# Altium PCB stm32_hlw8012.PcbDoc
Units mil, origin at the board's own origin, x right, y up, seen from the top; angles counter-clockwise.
Board outline 2529.53 x 3198.82 mil, 2 copper layers (Top Layer, Bottom Layer); 72 components, 57 nets, 229 pads, 39 vias.
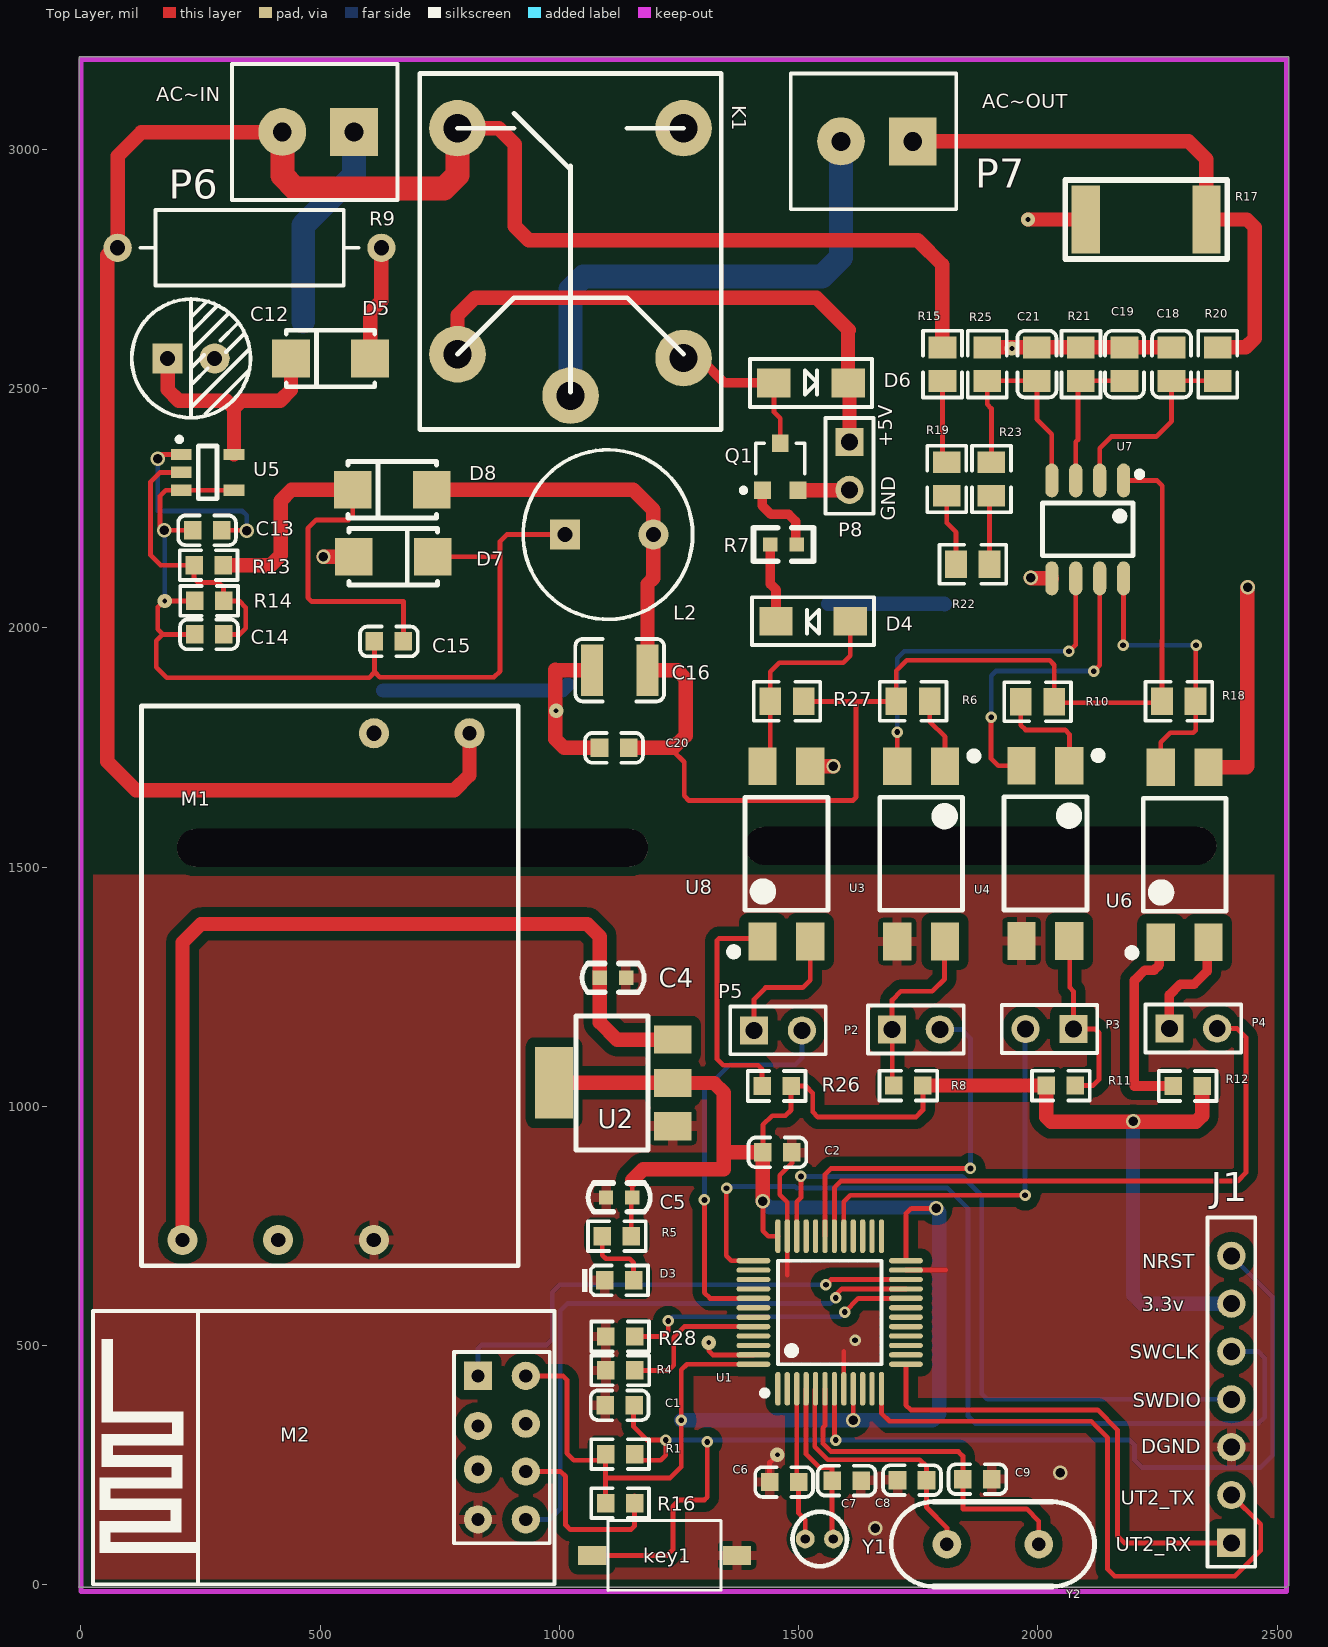
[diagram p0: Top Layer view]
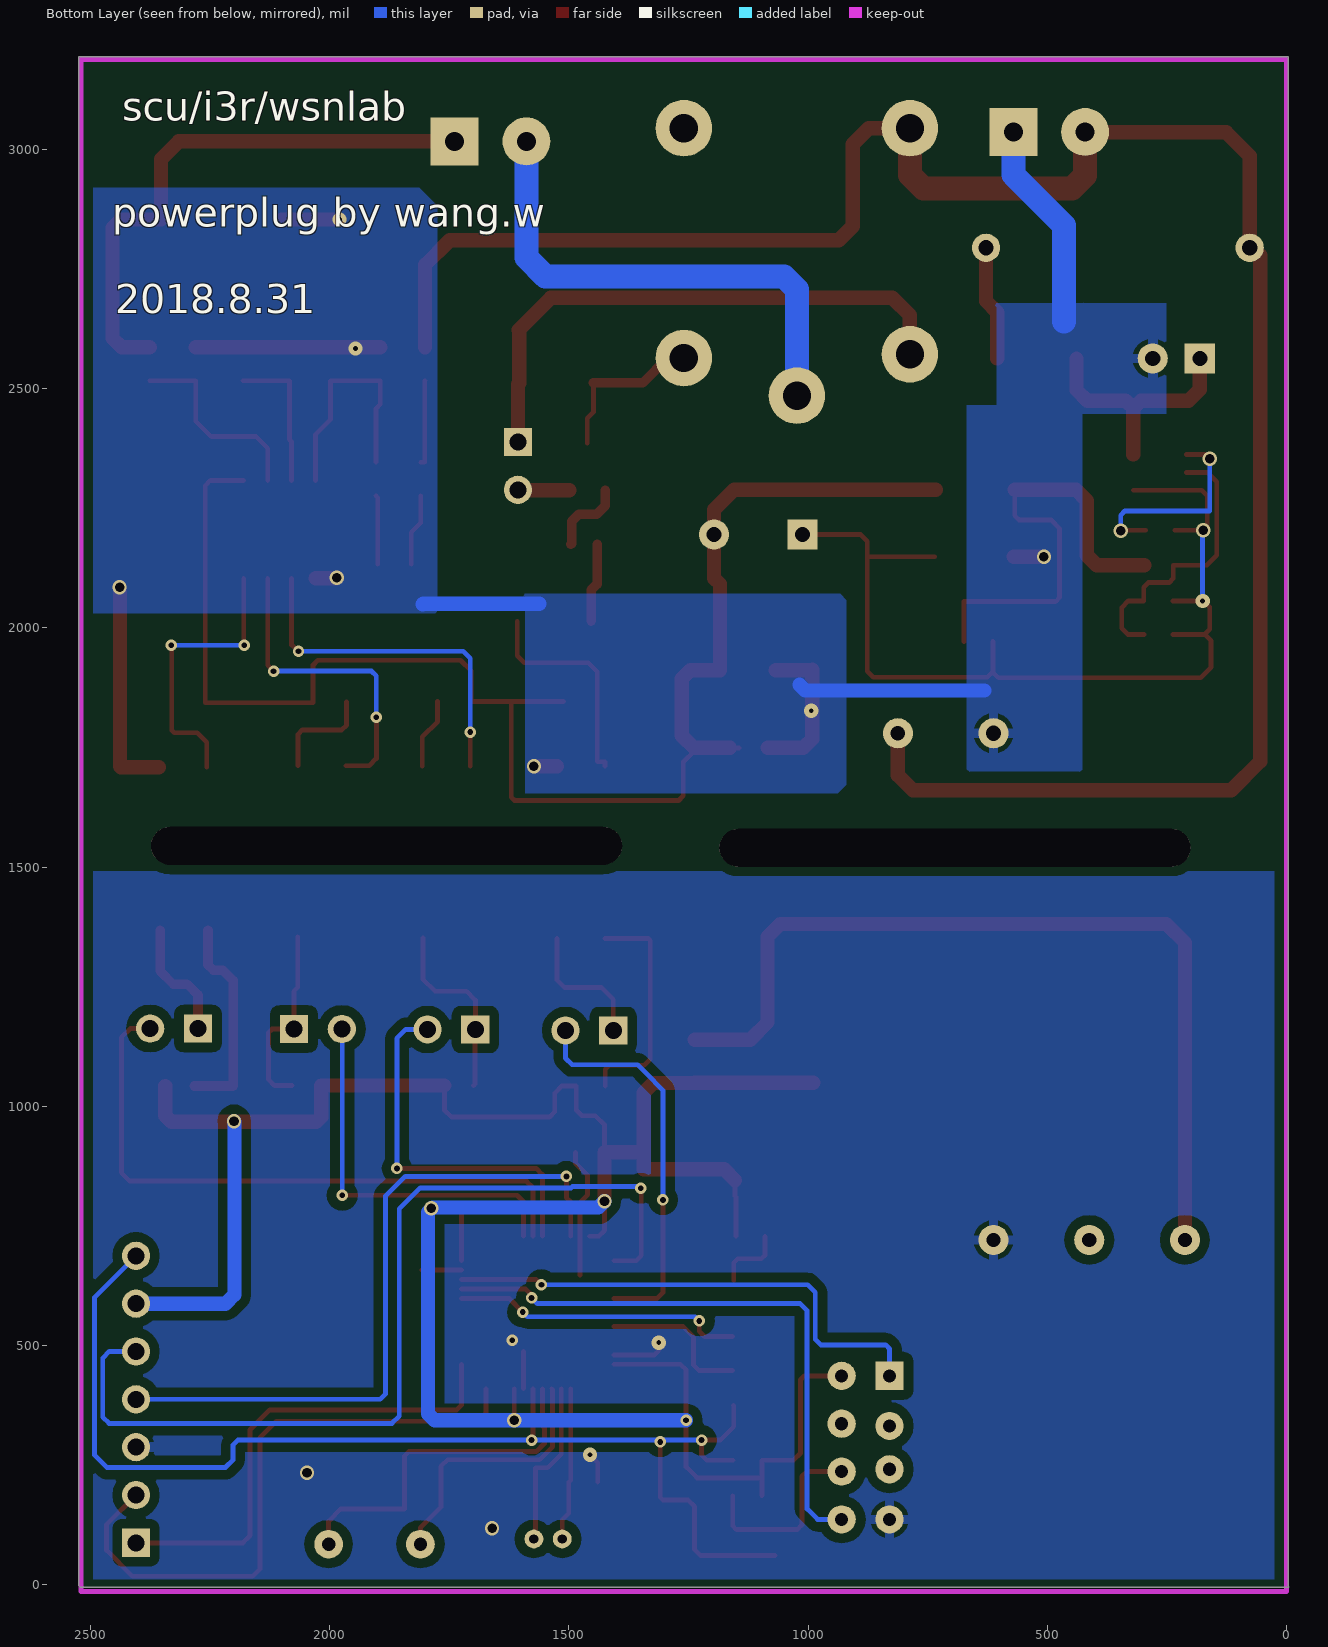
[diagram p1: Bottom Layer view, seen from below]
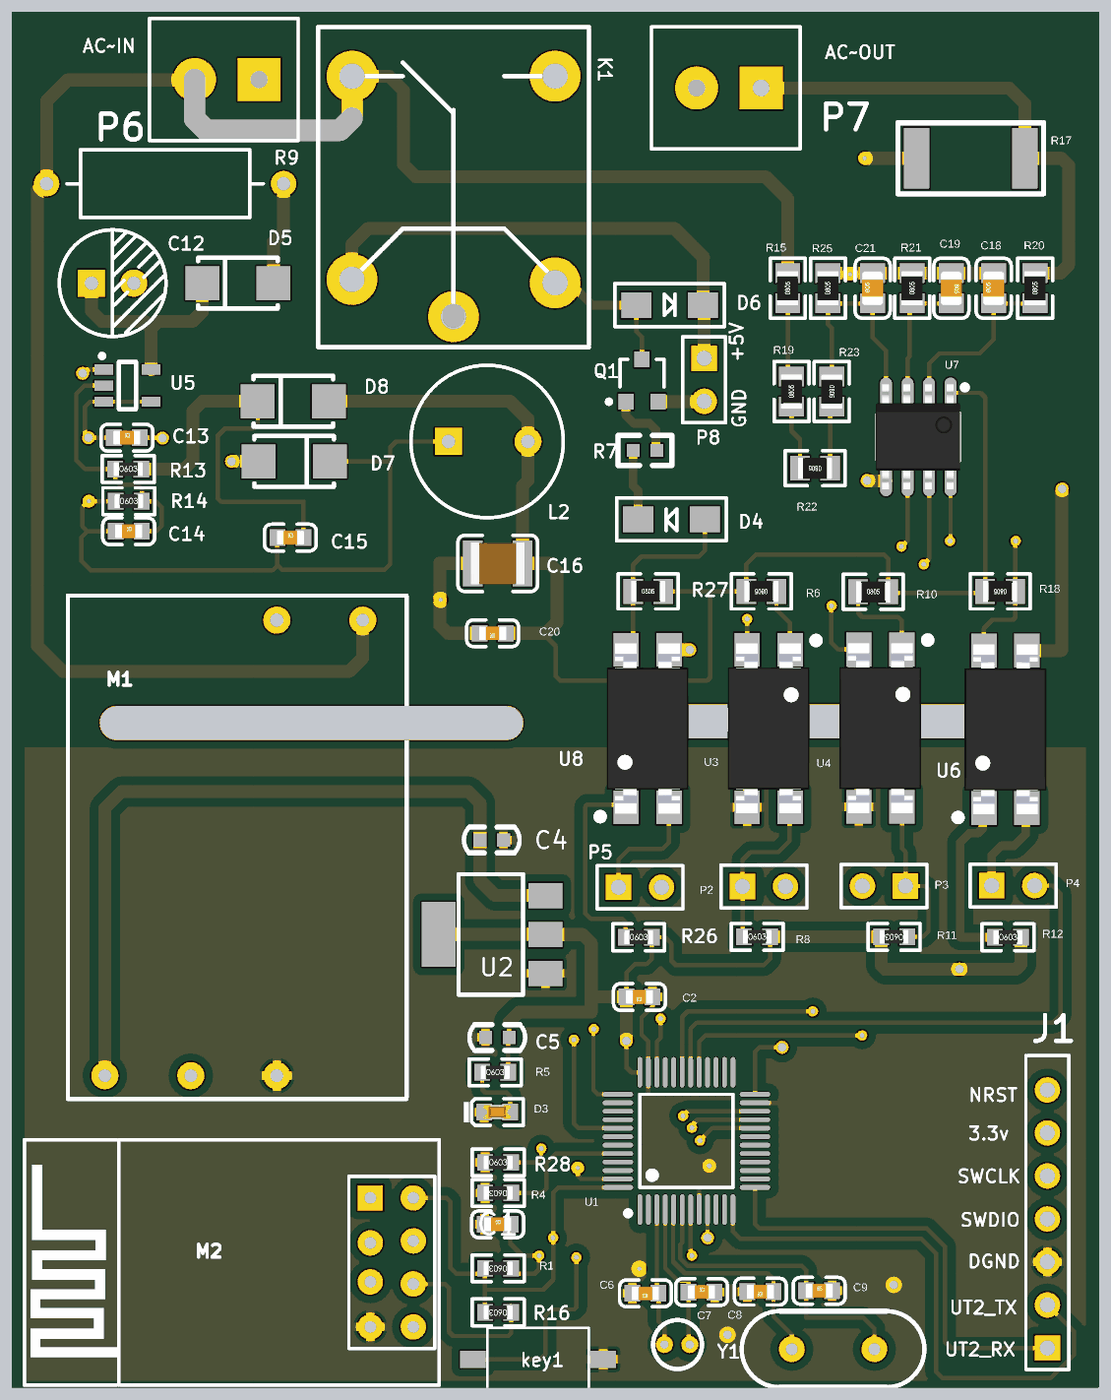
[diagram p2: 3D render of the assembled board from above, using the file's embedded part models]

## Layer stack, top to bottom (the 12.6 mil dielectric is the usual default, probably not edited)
Top Solder: solder mask 0.4, Solder Resist, Dk 3.5
Top Layer: signal copper 1.4
Dielectric 1: dielectric 12.6, FR-4, Dk 4.8
Bottom Layer: signal copper 1.4
Bottom Solder: solder mask 0.4, Solder Resist, Dk 3.5

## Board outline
2524.61,3193.9 2524.61,-1.97 2521.65,-4.92 -4.92,-4.92 -3.94,-3.94 -3.94,3193.9

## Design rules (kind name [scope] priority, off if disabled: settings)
Clearance Clearance_1 [InPolygon] p1: gap=20 ignorepadtopadclearanceinfootprint=FALSE except(0: Arc-Hole Track-Hole SMDPad-Hole THPad-Hole Via-Hole Fill-Hole Poly-Hole Region-Hole Text-Hole)
Clearance [All] p2: gap=7 ignorepadtopadclearanceinfootprint=FALSE except(0: Arc-Hole Track-Hole SMDPad-Hole THPad-Hole Via-Hole Fill-Hole Poly-Hole Region-Hole Text-Hole)
ComponentClearance [All] p1: gap=4 collisioncheckmode=3 verticalgap=4 showdistances=FALSE
DiffPairsRouting [All] p1: maxlimit=10 minlimit=10 mostfreqgap=10 toplayer_minwidth=10 toplayer_maxwidth=15 toplayer_prefwidth=15 bottomlayer_minwidth=10 bottomlayer_maxwidth=15 bottomlayer_prefwidth=15 maxuncoupledlength=500
HoleSize [All] p1: absolutevalues=TRUE maxlimit=500 minlimit=1 maxpercent=80.000 minpercent=20.000
HoleToHoleClearance [All] p1: gap=4 allowstackedmicrovias=TRUE
MinimumSolderMaskSliver [All] p1: minsoldermaskwidth=4
PolygonConnect PolygonConnect_1 [Isvia] p1: connectstyle=Direct reliefconductorwidth=10 reliefentries=4 polygonreliefangle="90 Angle" airgapwidth=10
PolygonConnect [All] p2: connectstyle=Relief reliefconductorwidth=20 reliefentries=4 polygonreliefangle="90 Angle" airgapwidth=10
RoutingVias [All] p1: holewidth=20 width=30 viastyle="Through Hole" minholewidth=10 minwidth=10 maxholewidth=28 maxwidth=50
SilkToSilkClearance [All] p1: silktosilkclearance=4
SilkToSolderMaskClearance [IsPad] p1: minsilkscreentomaskgap=0 clearancetoexposedcopper=TRUE
SolderMaskExpansion [All] p1: expansion=4
Width [All] p1: maxlimit=500 minlimit=10 preferedwidth=10 minimp=50.000000 maximp=50.000000 favimp=50.000000
23 further rules are at their usual default settings.

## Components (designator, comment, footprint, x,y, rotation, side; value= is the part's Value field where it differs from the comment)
C1 "0.1μF" LC-0603_C 1125.98,375 r0 top
C2 "0.1μF" LC-0603_C 1455.71,903.54 r180 top
C4 "104" 0603C 1106.3,1269.69 r180 top
C5 "104" 0603C 1130.91,808.07 r0 top
C6 "6pF" LC-0603_C 1469.69,214.57 r180 top
C7 "6pF" LC-0603_C 1600.2,217.52 r0 top
C8 "20pF" LC-0603_C 1737.01,218.5 r180 top
C9 "20pF" LC-0603_C 1873.82,220.47 r0 top
C12 "3.3μF/400V" CAP-ELECT-TH-6.3X7 230.31,2562.99 r0 top value=2.2μF/400V
C13 "2.2μF/10V" LC-0603_C 263.58,2203.74 r0 top value="100nF (104) ±10% 50V"
C14 "470pF" LC-0603_C 267.72,1986.22 r0 top value="100nF (104) ±10% 50V"
C15 "220nF" LC-0603_C 643.7,1971.46 r0 top value="100nF (104) ±10% 50V"
C16 "100μF" LC-1210_C 1125.98,1911.42 r0 top value="100nF (104) ±10% 50V"
C18 "33nF" LC-0805_C 2279.53,2551.18 r90 top value="100nF (104) ±10% 50V"
C19 "33nF" LC-0805_C 2181.1,2551.18 r270 top value="100nF (104) ±10% 50V"
C20 "0.1μF" LC-0603_C 1114.17,1749.02 r180 top value="100nF (104) ±10% 50V"
C21 "33nF" LC-0805_C 1998.03,2551.18 r90 top value="100nF (104) ±10% 50V"
D3 "POWER" LC-0603_LED_S1 1124.8,635.83 r0 top value=红色
D4 "IN4148" 1206D 1657.76,2043.78 r270 top
D5 "1N4007" LC-SMA(DO-214AC)_S1 521.65,2562.99 r0 top
D6 "" 1206D 1398.35,2481.81 r90 top
D7 "US1J(600V 1A)" LC-SMA(DO-214AC)_S1 652.56,2148.62 r180 top
D8 "1N4007" LC-SMA(DO-214AC)_S1 650.59,2288.39 r0 top
J1 "4P/NC" HDR1X7 2404.53,87.4 r90 top
K1 "Relay-5V" RLAYSPDT 983.27,2805.12 r90 top
key1 "SW" KEY-2 1371.06,61.02 r180 top
L2 "1mH" L-10X14 1101.38,2194.88 r0 top
M1 "ACDC_THX208based" ACDC_THX208 911.42,1836.61 r270 top
M2 "ESP-01&01S Module" "ESP-01&01S Module" 879.72,286.42 r90 top
P2 "Header" HDR1X2 1695.28,1160.43 r0 top
P3 "Header" HDR1X2 2074.41,1161.42 r180 top
P4 "Header" HDR1X2 2275,1162.4 r0 top
P5 "Header" HDR1X2 1406.89,1158.47 r0 top
P6 "Header" 3.81-2P 570.87,3037.4 r180 top
P7 "Header" 3.81-2P 1738.58,3017.73 r180 top
P8 "Header" HDR1X2 1606.3,2388.39 r270 top
Q1 "S8050" SOT-23 1461.61,2336.61 r0 top
R1 "10KΩ" LC-0603_R 1126.97,272.64 r180 top
R4 "10KΩ" LC-0603_R 1127.17,447.83 r180 top
R5 "1.5KΩ" LC-0603_R 1120.08,728.35 r0 top
R6 "1KΩ,1%" LC-0805_R 1739.17,1846.46 r180 top
R7 "Res2" 0603 1495.94,2174.21 r180 top value=4.7K
R8 "2.2KΩ" LC-0603_R 1729.53,1043.31 r0 top
R9 "39Ω/1W" R-1W-THT 352.36,2794.29 r0 top
R10 "1KΩ,1%" LC-0805_R 1999.41,1845.47 r0 top
R11 "2.2KΩ" LC-0603_R 2048.03,1043.31 r180 top
R12 "2.2KΩ" LC-0603_R 2312.99,1042.32 r0 top
R13 "5.49KΩ" LC-0603_R 266.73,2130.91 r0 top
R14 "4.99KΩ" LC-0603_R 267.91,2056.1 r0 top
R15 "470KΩ,1%" LC-0805_R 1800.59,2551.18 r90 top
R16 "4.7KΩ" LC-0603_R 1126.97,170.28 r180 top
R17 "2mΩ/25A" R2512 2226.38,2853.35 r180 top
R18 "1KΩ,1%" LC-0805_R 2294.88,1846.46 r180 top
R19 "470KΩ,1%" LC-0805_R 1809.45,2311.02 r90 top
R20 "1KΩ,1%" LC-0805_R 2375.98,2551.18 r90 top
R21 "1KΩ,1%" LC-0805_R 2089.98,2551.18 r90 top
R22 "470KΩ,1%" LC-0805_R 1864.17,2132.87 r180 top
R23 "470KΩ,1%" LC-0805_R 1902.95,2311.02 r270 top
R25 "1KΩ,1%" LC-0805_R 1894.09,2551.18 r90 top
R26 "2.2KΩ" LC-0603_R 1453.94,1042.32 r0 top
R27 "1KΩ,1%" LC-0805_R 1475.79,1846.46 r0 top
R28 "10KΩ" LC-0603_R 1126.97,518.7 r0 top
U1 "STM32F103C8T6" LC-LQFP-48_7x7x05P 1564.96,568.9 r0 top
U2 "LM1117-3.3V" SOT-223/P2.3 1125.98,1047.24 r180 top
U3 "PC817" LC-SMD-4 1756.1,1527.56 r270 top
U4 "PC817" LC-SMD-4 2015.95,1528.54 r270 top
U5 "MP150" LC-SOT-23-5 264.76,2324.8 r180 top
U6 "PC817" LC-SMD-4 2306.89,1525.59 r90 top
U7 "HLW8012" LC-SOP-8_150mil 2104.33,2205.71 r180 top
U8 "PC817" LC-SMD-4 1474.61,1527.56 r90 top
Y1 "32.768K" CRYSTAL 1522.83,95.47 r180 top
Y2 "8M" 49/U_N 1810.04,84.64 r0 top value="25MHz ±20ppm 20pF"

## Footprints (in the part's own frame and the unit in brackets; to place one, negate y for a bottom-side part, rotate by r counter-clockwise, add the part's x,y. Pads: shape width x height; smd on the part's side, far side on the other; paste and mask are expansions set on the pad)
3.81-2P [mil]
  rect 100x100 hole 39.37: 1(0,0.99)
  round 100 hole 39.37: 2(150,1)
  silkscreen extent -91,-141 255,143
49/U_N [mil]
  round 60 hole 28: 1(0,0) 2(192,0)
  silkscreen extent -116,-88 308,89, body extent -117,-88 309,89, height 512
0603 [mil]
  rect 30x30 smd: 1(0,0) 2(55,0)
  silkscreen extent -35,-35 90,35
0603C [mil]
  rect 30x30 smd: 1(21.61,1.26) 2(-33.39,1.26)
  silkscreen extent -71,-29 59,31
1206D [mil]
  rect 60x70 smd: 1(30,-50) 2(30,-205)
  silkscreen extent -20,-255 80,0
ACDC_THX208 [mm]
  round 1.6 hole 0.762: 1(1.45,-2.52) 3(28.35,-7.6) 4(28.35,-12.68) 5(28.35,-17.76)
  round 1.6 hole 0.8: 2(1.45,-7.6)
  silkscreen extent 0,-19.94 29.72,0.06
CAP-ELECT-TH-6.3X7 [mm]
  rect 1.6x1.6 hole 0.8: 1(-1.25,0)
  round 1.6 hole 0.8: 2(1.25,0)
  silkscreen extent -3.15,-3.15 3.15,3.15
CRYSTAL [mm]
  round 1 hole 0.5: 1(-1.27,0) 2(0.23,0)
  silkscreen extent -1.99,-1.44 0.9,1.44
"ESP-01&01S Module" [mm]
  rect 1.5x1.5 hole 0.7: 1(3.81,1.27)
  round 1.5 hole 0.7: 2(1.15,1.27) 3(-1.15,1.27) 4(-3.81,1.27) 5(3.81,-1.27) 6(1.27,-1.27) 7(-1.27,-1.27) 8(-3.81,-1.27)
  silkscreen extent -7.25,-2.79 7.25,21.71
HDR1X2 [mm] "Connector; Header; 2 Position"
  rect 1.5x1.5 hole 0.9: 1(0,0)
  round 1.5 hole 0.9: 2(2.54,0)
  silkscreen extent -1.27,-1.27 3.81,1.27
HDR1X7 [mm]
  rect 1.5x1.5 hole 0.9: 1(0,0)
  round 1.5 hole 0.9: 2(2.54,0) 3(5.08,0) 4(7.62,0) 5(10.16,0) 6(12.7,0) 7(15.24,0)
  silkscreen extent -1.27,-1.27 17.27,1.27
KEY-2 [mm]
  rect 1.5x1 smd: 1(-0.005,-0.001) 2(7.685,-0.001)
  silkscreen extent 0.85,-1.85 6.85,1.86
L-10X14 [mm]
  rect 1.6x1.6 hole 0.8: 1(-2.286,0)
  round 1.6 hole 0.8: 2(2.413,0)
  silkscreen extent -4.5,-4.5 4.5,4.5
LC-0603_C [mm]
  rect 0.93x0.98 smd: 1(-0.77,0) 2(0.77,0)
  silkscreen extent -1.53,-0.79 1.54,0.79, body extent -0.8,-0.4 0.8,0.4, height 0.3
LC-0603_LED_S1 [mm]
  rect 0.93x0.98 smd: A(0.77,0) K(-0.77,0)
  silkscreen extent -1.98,-0.79 1.53,0.79, body extent -0.8,-0.4 0.8,0.4, height 0.6
LC-0603_R [mm]
  rect 0.93x0.98 smd: 1(-0.77,0) 2(0.77,0)
  silkscreen extent -1.54,-0.79 1.53,0.79, body extent -0.85,-0.4 0.85,0.4, height 0.56
LC-0805_C [mm]
  rect 1.16x1.47 smd: 1(-0.89,0) 2(0.89,0)
  silkscreen extent -1.77,-1.04 1.77,1.04, body extent -1,-0.62 1,0.63, height 0.77
LC-0805_R [mm]
  rect 1.16x1.47 smd: 1(-0.89,0) 2(0.89,0)
  silkscreen extent -1.77,-1.03 1.77,1.04, body extent -1,-0.62 1,0.63, height 0.49
LC-1210_C [mm]
  rect 1.16x2.72 smd: 1(-1.475,0) 2(1.475,0)
  silkscreen extent -2.36,-1.66 2.35,1.66, body extent -1.6,-1.25 1.6,1.25, height 1.3
LC-LQFP-48_7x7x05P [mm]
  oval 0.28x1.8 smd mask+0.051: 1(-2.75,-4.05) 2(-2.25,-4.05) 3(-1.75,-4.05) 4(-1.25,-4.05) 5(-0.75,-4.05) 6(-0.25,-4.05) 7(0.25,-4.05) 8(0.75,-4.05) 9(1.25,-4.05) 10(1.75,-4.05) 11(2.25,-4.05) 12(2.75,-4.05) 25(2.75,4.05) 26(2.25,4.05) 27(1.75,4.05) 28(1.25,4.05) 29(0.75,4.05) 30(0.25,4.05) 31(-0.25,4.05) 32(-0.75,4.05) 33(-1.25,4.05) 34(-1.75,4.05) 35(-2.25,4.05) 36(-2.75,4.05)
  oval 1.8x0.28 smd mask+0.051: 13(4.05,-2.75) 14(4.05,-2.25) 15(4.05,-1.75) 16(4.05,-1.25) 17(4.05,-0.75) 18(4.05,-0.25) 19(4.05,0.25) 20(4.05,0.75) 21(4.05,1.25) 22(4.05,1.75) 23(4.05,2.25) 24(4.05,2.75) 37(-4.05,2.75) 38(-4.05,2.25) 39(-4.05,1.75) 40(-4.05,1.25) 41(-4.05,0.75) 42(-4.05,0.25) 43(-4.05,-0.25) 44(-4.05,-0.75) 45(-4.05,-1.25) 46(-4.05,-1.75) 47(-4.05,-2.25) 48(-4.05,-2.75)
  silkscreen extent -3.6,-4.42 2.75,2.75
LC-SMA(DO-214AC)_S1 [mm]
  rect 2x2 smd: 1(2.1,0) 2(-2.1,0)
  silkscreen extent -2.35,-1.5 2.35,1.5
LC-SMD-4 [mm]
  rect 2x1.5 smd: 1(-4.65,1.27) 2(-4.65,-1.27) 3(4.65,-1.27) 4(4.65,1.27)
  silkscreen extent -5.4,-2.2 3,3, body extent -5.02,-2.42 5.01,2.42, height 3.9
LC-SOP-8_150mil [mm]
  oval 0.7x1.8 smd: 1(-1.905,-2.6) 2(-0.635,-2.6) 3(0.635,-2.6) 4(1.905,-2.6) 5(1.905,2.6) 6(0.635,2.6) 7(-0.635,2.6) 8(-1.905,2.6)
  silkscreen extent -2.9,-3.07 2.4,1.4, body extent -2.5,-3.1 2.5,3.1, height 1.75
LC-SOT-23-5 [mm]
  rect 1.1x0.6 smd: 1(1.4,-0.95) 2(1.4,0) 3(1.4,0.95) 4(-1.4,0.95) 5(-1.4,-0.95)
  silkscreen extent -0.5,-1.87 1.62,1.4
R2512 [mm]
  rect 1.5x3.6 smd: 1(-3.2,0) 2(3.2,0)
  silkscreen extent -4.3,-2.1 4.3,2.1
R-1W-THT [mm]
  round 1.5 / inner oval 1.5x2 / far side round 1.5 hole 0.8: 1(-7,0)
  round 1.5 hole 0.8: 2(7,0)
  silkscreen extent -5.8,-2 5.8,2
RLAYSPDT [mm]
  round 3 hole 1.5: 1(-8.128,-1.016) 2(6.072,4.984) 3(6.072,-7.016) 4(-6.128,-7.016) 5(-5.928,4.984)
  silkscreen extent -9.93,-9.02 8.97,6.98
SOT-23 [mm]
  rect 0.9x0.95 smd: 1(-0.95,-1.25) 2(0.95,-1.25) 3(0,1.25)
  silkscreen extent -2.07,-1.37 1.3,1.25
SOT-223/P2.3 [mil]
  rect 79x59 smd: 1(-111,89.1) 2(-111,-1.45) 3(-111,-92)
  rect 79x150 smd: 2(137,-1.9)
  silkscreen extent -59,-141 91,139

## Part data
C1 C2 C6 C7 C8 C9: library part Cap, "贴片电容"
C4 C5: library part CAP, "Capacitor"
C12: library part "Cap Pol1", "直插电解电容"
C13 C14 C15 C16 C18 C19 C20 C21: library part CAP, "贴片电容"
D3: library part LED1, "发光二极管"
D4 D6: library part Diode, "Default Diode", PackageDocument=Sep-1996
D5 D7 D8: library part "Diode 1N5408", "贴片二极管"
J1: library part "Header 7", "接口"
K1: library part Relay-SPDT, "Single-Pole Dual-Throw Relay"
key1: "Switch"
L2: library part IND_8, "直插绕线电感"
M1: library part ACDC, "THX208Based"
P2 P3 P4 P5 P6 P7 P8: library part "Header 2", "Header, 2-Pin"
Q1: library part NPN, "NPN Bipolar Transistor"
R1 R4 R5 R6 R8 R9 R10 R11 R12 R13 R14 R15 R17 R18 R19 R20 R21 R22 R23 R25 R26 R27 R28: library part 电阻, "贴片电阻"
R7: "Resistor"
R16: library part "0805 62KΩ (6202) 1%", "贴片电阻", Package=0402, SuppliersPartNumber=C17783
U1: library part STM32F103CBT6, "IC"
U2: library part 1117
U3 U4 U6 U8: library part PS2501L-1-F3-A, "IC"
U5 U7: "IC"
Y1: library part XTAL, "Crystal Oscillator"
Y2: library part XTAL_1, "晶振（直插）"

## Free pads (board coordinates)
  oval 984.25x78.74 hole 78.74 slot 984.25 at 0 deg paste+0: 0(692.91,1540.35) 0(1880.91,1544.29)

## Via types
v1: diameter 24, hole 12, Top Layer to Bottom Layer, 20 vias
v2: diameter 30, hole 20, Top Layer to Bottom Layer, 13 vias
v3: diameter 30, hole 10, Top Layer to Bottom Layer, 6 vias

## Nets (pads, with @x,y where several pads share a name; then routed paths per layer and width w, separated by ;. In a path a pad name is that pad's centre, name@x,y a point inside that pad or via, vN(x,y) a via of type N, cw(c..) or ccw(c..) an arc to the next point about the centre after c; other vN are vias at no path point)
+3.3V: C2.2 C5.1 J1.6 M2.5 R1.2 R5.2 R8.2 R11.2 R12.2 R16.2 R26.2 U1.9 U1.24 U1.36 U1.48 U2.2 | length 5489.6
  Top Layer w10: M2.5 1007.48,436.42 1015.75,428.15 1015.75,274.61 1030.51,259.84 1096.46,259.84 1096.46,223.03 ; R16.2@1096.65,186.02 1096.46,186.22 1096.46,223.03 ; R5.2 1150.39,810 1152.52,812.13 1152.52,845.47 ; U1.48 1266.73,460.63 1254.92,448.82 v1(1254.92,343.5) 1254.92,246.06 1231.89,223.03 1096.46,223.03 ; v2(1425.39,801.38) 1425.39,739.96 1437.01,728.35 U1.36 ; C2.2 1425.39,960.83 1444.88,980.32 1472.44,980.32 1484.25,992.13 R26.2 1514.76,1042.32 1529.53,1027.56 1529.53,988.19 1540.35,977.36 1745.08,977.36 1759.84,992.13 R8.2 ; v2(1614.17,343.5) U1.9 ; U1.24 1724.41,775.59 1735.24,786.42 v2(1787.4,786.42)
  Top Layer w30: U2.2@988.98,1049.14 1236.54,1049.14 1236.98,1048.69 1323.35,1048.69 1343.5,1028.54 1343.5,904.53 ; 1152.52,845.47 1175.16,868.11 1343.5,868.11 1343.5,904.53 ; v2(1425.39,801.38) C2.2 1344.49,903.54 1343.5,904.53 ; R8.2 R11.2 2017.72,977.36 2027.56,967.52 2330.71,967.52 2343.31,980.12 R12.2
  Bottom Layer w30: v1(1254.92,343.5) v2(1614.17,343.5) 1780.51,343.5 1794.29,357.28 1794.29,778.54 1784.45,788.39 1438.39,788.39 v2(1425.39,801.38) ; v2(2199.8,968.5) 2198.82,967.52 2198.82,606.3 2217.72,587.4 J1.6
+5V: C4.1 M1.5 U2.3 | length 1867.5
  Top Layer w30: M1.5 212.2,1342.12 250.98,1380.91 1058.07,1380.91 1084.69,1354.29 C4.1 1084.69,1175.16 1120.6,1139.24 U2.3
A+5V: C16.2 C20.1 D8.1 L2.2 R6.2 R10.2 R18.2 R27.2 U7.1 | length 3277.6
  Top Layer w10: C20.1 1163.07,1749.01 ; 1238.19,1749.01 1238.19,1742.13 1260.83,1719.49 1260.83,1648.84 1270.67,1639 1613.41,1639 1620.08,1645.67 1620.08,1845.02 1619.09,1846 ; R27.2 1511.28,1846 1619.09,1846 ; U7.1 2249.02,2308.07 2260,2297.09 2260,1974 2259.84,1973.84 R18.2 2259.84,1843.24 2034.45,1843.24 R10.2 2034.45,1922.24 2024.61,1932.09 1726.38,1932.09 1704.13,1909.84 R6.2 1704.13,1846 1619.09,1846
  Top Layer w30: D8.1 1154.53,2288.38 1196.38,2246.54 L2.2 1196.38,2103.86 1184.05,2091.54 C16.2 1246.06,1911.42 1263.78,1893.7 1263.78,1774.61 1238.19,1749.01 1163.07,1749.01
AC220V-L: K1.2 M1.1 P6.2 R9.1 R15.2 | length 4507.8
  Top Layer w30: P6.2 419.9,3035.43 125.98,3035.43 76.77,2986.22 R9.1 70.87,2794.29 55.12,2778.54 55.12,1720.47 115.16,1660.43 780.51,1660.43 812.2,1692.12 M1.1 ; K1.2 873.15,3044.17 906.5,3010.83 906.5,2839.57 936.02,2810.04 1749.02,2810.04 1800.59,2758.46 R15.2
  Top Layer w50: P6.2 420.87,2945.28 447.83,2918.31 758.86,2918.31 787.05,2946.5 K1.2
AC220V-N: C12.2 C16.1 C18.2 C19.1 C20.2 C21.2 D7.1 M1.2 P6.1 R17.2 R21.2 R25.2 U6.3 U7.5 U8.3 | length 2515.8
  Top Layer w30: v2(506.89,2148.62) D7.1 ; C16.1 992.13,1911.42 991.14,1912.4 991.14,1767.72 1009.84,1749.01 C20.2 ; U8.3 v2(1572.83,1710.63) ; R25.2 C21.2 R21.2 C19.1 C18.2 ; v3(1979.33,2853.35) R17.2 ; v2(1985.24,2104.33) 1986.22,2103.35 U7.5 ; U6.3 2436.02,1708.66 2437.99,1710.63 2437.99,2083.66 v2(2438.98,2084.65)
  Bottom Layer w30: 631.89,1869.09 1005.91,1869.09 1017.72,1880.91 ; 1562.01,2050.2 1804.13,2050.2 1805.12,2049.21
  Bottom Layer w50: 464.57,2639.76 464.57,2840.55 570.87,2946.85 P6.1
  other v3: 993.11,1826.77 1945.87,2583.66
BOOT0: R4.1 U1.44 | length 320.3
  Top Layer w10: R4.1 1228.35,447.84 1239.17,458.66 1239.17,517.3 1261.25,539.37 U1.44
CF: U3.2 U7.6 | length 749.7
  Top Layer w10: U3.2 v1(1706.1,1782.09) ; v1(2064.96,1950.79) 2065.94,1950.79 2079.33,1964.17 U7.6
  Bottom Layer w10: v1(1706.1,1782.09) 1706.1,1936.42 1720.47,1950.79 2007.87,1950.79 v1(2064.96,1950.79)
CF1: U4.2 U7.7 | length 660.8
  Top Layer w10: v1(1902.56,1812.99) 1902,1812.43 1902,1726.94 1917.32,1711.61 U4.2 ; v1(2117.13,1909.45) 2129.33,1921.65 U7.7
  Bottom Layer w10: v1(1902.56,1812.99) 1902.56,1899.61 1912.4,1909.45 v1(2117.13,1909.45)
CTL_Pin: P5.2 U1.41 | length 820
  Top Layer w10: v1(1303.15,804.13) 1303.15,610.24 1314.96,598.43 U1.41
  Bottom Layer w10: v1(1303.15,804.13) 1303.15,1033.47 1338.58,1068.9 1356.3,1086.61 1493.11,1086.61 1506.89,1100.39 P5.2
CTL_Pin_AC: D4.1 R27.1 U8.4 | length 466.6
  Top Layer w10: U8.4 1424.61,1720 1440.75,1720 R27.1 1440.75,1908.27 1459.65,1927.16 1592.99,1927.16 1607.76,1941.93 D4.1
DGND: C1.1 C2.1 C4.2 C5.2 C6.2 C7.2 C8.2 C9.2 D3.K J1.3 key1.1 M1.3 M2.4 R4.2 R28.1 U1.8 U1.23 U1.35 U1.47 U2.1 U3.3 U4.3 | length 612.1
  Top Layer w10: v3(1312.01,505.91) 1312.01,489.17 1320.86,480.32 U1.47 ; C6.2 1439.37,255.31 v3(1455.71,271.65) ; 1476.38,646.65 U1.35 1476.38,799.21 1460.63,814.96 1460.63,855.31 1486.02,880.71 C2.1 ; U1.8 1594.49,487.2 ; U1.23 1807.08,657.48
  other v1: 1618.11,510.83
  other v2: 1660.43,118.11 2047.24,234.25
NetC12_1: C12.1 D5.2 U5.5 | length 517.4
  Top Layer w30: C12.1 181.1,2498.03 204.72,2474.41 304.13,2474.41 319.88,2458.66 ; U5.5 319.88,2458.66 ; D5.2 438.98,2497.05 416.34,2474.41 335.63,2474.41 319.88,2458.66
NetC13_1: C13.1 C14.1 C15.1 D7.2 L2.1 R14.1 U5.3 U5.4 | length 2088.3
  Top Layer w10: C13.1 v2(174.21,2203.74) 165.35,2212.6 165.35,2275.59 177.16,2287.4 U5.3 U5.4 ; C14.1 171.26,1986.22 ; R14.1 v3(175.2,2056.1) 173.23,2056.1 160.43,2043.31 160.43,1997.05 171.26,1986.22 ; C15.1 613.58,1971.26 613.58,1908.07 ; D7.2 873.03,2148.62 875.98,2151.57 ; L2.1 889.76,2194.88 875.98,2181.1 875.98,2151.57 ; 171.26,1986.22 157.48,1972.44 157.48,1917.32 179.13,1895.67 602.36,1895.67 613.58,1906.89 613.58,1908.07 ; 613.58,1908.07 625,1896.65 863.19,1896.65 875.98,1909.45 875.98,2151.57
  Bottom Layer w10: v2(174.21,2203.74) 175.2,2202.76 v3(175.2,2056.1)
NetC13_2: C13.2 U5.1 | length 437.3
  Top Layer w10: v2(160.43,2353.35) 169.29,2362.2 U5.1 ; C13.2 345.47,2203.74 v2(346.46,2202.76)
  Bottom Layer w10: v2(160.43,2353.35) 160.43,2244.09 337.6,2244.09 346.46,2235.24 v2(346.46,2202.76)
NetC14_2: C14.2 R13.1 R14.2 U5.2 | length 597.8
  Top Layer w10: U5.2 165.35,2324.8 145.67,2305.12 145.67,2151.57 166.34,2130.91 R13.1 236.42,2103.15 245.08,2094.49 288.39,2094.49 298.23,2084.65 R14.2 330.71,2056.1 344.49,2042.32 344.49,1999.02 331.69,1986.22 C14.2
NetC15_2: C15.2 D8.2 R13.2 | length 992.7
  Top Layer w10: D8.2 567.91,2234.25 559.06,2225.39 492.13,2225.39 474.41,2207.68 474.41,2062.99 482.48,2054.92 674.01,2054.92 C15.2
  Top Layer w30: R13.2 396.65,2130.91 417.32,2151.58 417.32,2265.75 439.96,2288.38 D8.2
NetC18_1: C18.1 R20.1 U7.2 | length 421.5
  Top Layer w10: U7.2 2129.33,2375.39 2153.54,2399.61 2247.05,2399.61 2279.53,2432.09 C18.1 R20.1
NetC19_2: C19.2 R21.1 U7.3 | length 307.1
  Top Layer w10: U7.3 2079.33,2388.38 2084,2393.05 2084,2516.14 R21.1 C19.2
NetC21_1: C21.1 R23.1 R25.1 U7.4 | length 498.7
  Top Layer w10: R23.1 1902.95,2458.27 1894.09,2467.13 R25.1 C21.1 1998.03,2436.02 2029.33,2404.72 U7.4
NetD3_A: D3.A R5.1 | length 148.4
  Top Layer w10: R5.1 1089.76,688.78 1097.44,681.1 1146.65,681.1 1155.12,672.64 D3.A
NetD4_2: D4.2 R7.2 | length 165.3
  Top Layer w20: R7.2 1440.94,2091.53 1452.76,2079.72 D4.2
NetD5_1: D5.1 R9.2 | length 241.1
  Top Layer w30: D5.1 604.33,2659.45 627.95,2683.07 R9.2
NetD6_1: D6.1 K1.4 Q1.3 | length 341.9
  Top Layer w10: D6.1 1448.35,2451.26 1461.61,2437.99 Q1.3
  Top Layer w20: K1.4 1293.42,2563.86 1345.47,2511.81 D6.1
NetD6_2: D6.2 K1.5 P8.1 | length 1178.4
  Top Layer w30: K1.5 787.05,2653.19 823.82,2689.96 1537.4,2689.96 1604.8,2622.56 1603.35,2621.1 D6.2 1606.3,2508.86 P8.1
NetK1_1: K1.1 P7.2 | length 1058.1
  Bottom Layer w50: K1.1 1023.27,2707.32 1050.2,2734.25 1549.21,2734.25 1588.58,2773.62 P7.2
NetM2_7: M2.7 R16.1 | length 403.5
  Top Layer w10: M2.7 1002.76,236.42 1012.8,226.38 1012.8,125 1022.64,115.16 1149.61,115.16 1157.28,122.83 R16.1 R16.1@1157.28,186.02
NetP2_1: P2.1 R8.1 U3.4 | length 394.7
  Top Layer w10: R8.1 1695.87,1046.65 1695.87,1159.84 P2.1 1695.28,1221.85 1713.58,1240.16 1779.53,1240.16 1804.92,1265.55 U3.4@1804.92,1352.36
NetP3_1: P3.1 R11.1 U4.4 | length 405.2
  Top Layer w10: U4.4@2066.73,1354.33 2066.73,1248.23 2074.41,1240.55 P3.1 2120.08,1161.42 2127.95,1153.54 2127.95,1056.1 2115.16,1043.31 R11.1
NetP4_1: P4.1 U6.2 | length 255.8
  Top Layer w20: P4.1 2275,1232.68 2297.24,1254.92 2326.77,1254.92 2354.13,1282.28 U6.2@2354.13,1368.11
NetP5_1: P5.1 U8.2 | length 286.2
  Top Layer w10: P5.1 1406.89,1223.82 1431.1,1248.03 1508.86,1248.03 1524.41,1263.58 U8.2@1524.41,1350.39
NetP7_1: P7.1 R17.1 R20.2 | length 1180.5
  Top Layer w30: P7.1 2314.94,3016.75 2352.36,2979.33 R17.1 2437.01,2853.35 2453.74,2836.61 2453.74,2605.31 2434.65,2586.22 R20.2
NetP8_2: P8.2 Q1.2 | length 107.7
  Top Layer w30: Q1.2 1605.32,2287.4 P8.2
NetQ1_1: Q1.1 R7.1 | length 164.8
  Top Layer w20: Q1.1 1424.21,2254.92 1441.93,2237.2 1479.33,2237.2 1494.09,2222.44 1494.09,2176.06 R7.1
NetR6_1: R6.1 U3.1 | length 149
  Top Layer w10: R6.1 1774.21,1803.89 1806.1,1772 U3.1
NetR10_1: R10.1 U4.1 | length 224.4
  Top Layer w10: R10.1 1964.37,1796.46 1974.41,1786.42 2057.09,1786.42 2065.94,1777.56 U4.1
NetR12_1: R12.1 U6.1 | length 439.9
  Top Layer w20: U6.1@2254.13,1368.11 2254.13,1295.47 2243.11,1284.45 2223.43,1284.45 2201.77,1262.8 2201.77,1042.32 R12.1
NetR15_1: R15.1 R19.2 | length 178.9
  Top Layer w10: R15.1 1801,2516.14 1801,2346.06 R19.2
NetR19_1: R19.1 R22.2 | length 151.3
  Top Layer w10: R19.1 1809.45,2219.09 1829.13,2199.41 R22.2
NetR22_1: R22.1 R23.2 | length 144.7
  Top Layer w10: R22.1 1899.21,2272.24 R23.2
NetR26_1: R26.1 U8.1 | length 482
  Top Layer w10: R26.1 1423.62,1077.36 1415.35,1085.63 1342.52,1085.63 1329.72,1098.43 1329.72,1346.46 1333.66,1350.39 U8.1@1424.41,1350.39
NetR28_2: R28.2 U1.20 | length 612.8
  Top Layer w10: R28.2 1216.53,518.7 1227.36,529.53 v1(1227.36,551.18) ; v1(1596.46,569.88) 1625,598.43 U1.20
  Bottom Layer w10: v1(1227.36,551.18) 1236.22,560.04 1586.61,560.04 v1(1596.46,569.88)
NRST: C1.2 J1.7 key1.2 R1.1 U1.7 | length 2571.4
  Top Layer w10: key1.2 1225.42,61.05 1237.2,72.83 1237.2,163.39 1250.98,177.17 1303.15,177.17 1309.06,183.07 v1(1309.06,298.23) ; C1.2 1155.12,375 1155.12,330.32 1183.27,302.17 v1(1222.44,302.17) 1222.44,270.67 1211.61,259.84 R1.1@1157.09,259.84 ; U1.7 1574.8,305.12 v1(1577.76,302.17)
  Bottom Layer w10: v1(1222.44,302.17) 1305.12,302.17 v1(1309.06,298.23) 1312.99,302.17 v1(1577.76,302.17) 2191.93,302.17 2201.77,292.32 2201.77,260.75 2217.52,245 2465.47,245 2491.14,270.67 2491.14,600.79 J1.7
OSC32_IN: C6.1 U1.3 Y1.2 | length 321.3
  Top Layer w10: U1.3 1496.06,218.5 C6.1 1500,149.61 1513.78,135.83 Y1.2
OSC32_OUT: C7.1 U1.4 Y1.1 | length 352.7
  Top Layer w10: U1.4 1515.75,272.64 1544.22,244.17 1569.88,244.17 C7.1 1569.88,98.42 Y1.1
OSC_IN: C8.1 U1.5 Y2.1 | length 552.6
  Top Layer w10: U1.5 1533.8,407.82 1533.8,288.14 1560.77,261.17 1753.2,261.17 1767.32,247.05 C8.1 1767.32,161.81 1810.04,119.09 Y2.1
OSC_OUT: C9.1 U1.6 Y2.2 | length 747.3
  Top Layer w10: U1.6 1555.12,332.17 1550.8,327.85 1550.8,295.18 1567.81,278.17 1834.04,278.17 1843.5,268.7 C9.1 1843.5,158.46 1976.38,158.46 2002.04,132.8 Y2.2
PA8: P3.2 U1.29 | length 804.3
  Top Layer w10: U1.29 1594.49,800.2 1608.27,813.98 v1(1973.43,813.98)
  Bottom Layer w10: v1(1973.43,813.98) 1973.43,1160.43 P3.2
PA9: P4.2 U1.30 | length 1324.9
  Top Layer w10: U1.30 1574.8,829.72 1588.58,843.5 2417.32,843.5 2435.04,861.22 2435.04,1143.7 2416.34,1162.4 P4.2
PA10: P2.2 U1.31 | length 781.7
  Top Layer w10: U1.31 1555.12,857.28 1567.91,870.08 v1(1859.25,870.08)
  Bottom Layer w10: P2.2 1840.55,1160.43 1859.25,1141.73 v1(1859.25,870.08)
PB10: M2.8 U1.21 | length 1242.8
  Top Layer w10: v1(1577.76,599.41) 1574.8,602.36 1590.55,618.11 U1.21
  Bottom Layer w10: M2.8 979.92,136.42 1001.97,158.46 1001.97,572.83 1016.73,587.6 1565.94,587.6 v1(1577.76,599.41)
PB11: M2.1 U1.22 | length 1069.1
  Top Layer w10: v1(1557.09,626.97) 1567.91,637.8 U1.22
  Bottom Layer w10: M2.1 829.72,493.11 837.6,500.98 973.43,500.98 984.97,512.53 984.97,611.22 1000.72,626.97 v1(1557.09,626.97)
SEL: R18.1 U6.4 U7.8 | length 605.1
  Top Layer w10: v1(2178.15,1963.58) 2179.33,1964.76 U7.8 ; U6.4 2256.89,1760.83 2276.57,1780.51 2324.8,1780.51 2329.92,1785.63 R18.1 v1@2329.92,1962.4
  Bottom Layer w10: v1(2178.15,1963.58) v1(2330.71,1963.58)
SWCLK: J1.5 U1.37 | length 1991.8
  Top Layer w10: v1(1349.41,828.74) 1348.58,827.91 1348.58,687.84 1359.25,677.17 U1.37
  Bottom Layer w10: v1(1349.41,828.74) 1352.79,832.12 1492.21,832.12 1494.98,829.35 1810.42,829.35 1854.33,785.43 1854.33,352.36 1869.69,337 2461.02,337 2474.14,350.13 2474.14,473.69 2460.43,487.4 J1.5
SWDIO: J1.4 U1.34 | length 1463.7
  Top Layer w10: U1.34 1496.06,800.2 1504.92,809.06 v1(1504.92,853.35)
  Bottom Layer w10: v1(1504.92,853.35) 1842.04,853.35 1882.87,812.52 1882.87,398.62 1894.09,387.4 J1.4
USART2_RX: J1.1 U1.13 | length 1014.7
  Top Layer w10: U1.13 1724.41,375 1734.25,365.16 2125,365.16 2166.34,323.82 2166.34,102.17 2181.1,87.4 J1.1
USART2_TX: J1.2 U1.12 | length 1309.4
  Top Layer w10: U1.12 1673.23,358.27 1689.96,341.53 2111.22,341.53 2145.67,307.09 2145.67,32.48 2160.43,17.72 2412.01,17.72 2466,71.71 2466,125.93 J1.2
VBAT: U1.1
pads on no net: K1.3 M1.4 M2.2 M2.3 M2.6 U1.2 U1.10 U1.11 U1.14 U1.15 U1.16 U1.17 U1.18 U1.19 U1.25 U1.26 U1.27 U1.28 U1.32 U1.33 U1.38 U1.39 U1.40 U1.42 U1.43 U1.45 U1.46

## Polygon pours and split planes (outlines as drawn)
DGND on Bottom Layer "Top Layer-No Net 1" (solid, remove dead copper, pour order 82): -30.51,1480.32 -19.69,1491.14 2843.5,1491.14 2843.5,171.26 2498.03,-174.21 -59.06,-174.21 -59.06,1448.82 -20.67,1487.2
AC220V-N on Bottom Layer "Top Layer-No Net 1" (solid, remove dead copper, pour order 38): 662.4,1698.82 668.31,1704.72 668.31,2465.55 408.46,2465.55 427.17,2446.85 427.17,1703.74 432.09,1698.82 433.07,1699.8 660.43,1699.8
AC220V-N on Bottom Layer "Top Layer-No Net 1" (solid, remove dead copper, pour order 36): 250.98,2447.83 250.98,2678.15 424.21,2678.15 425.2,2679.13 426.18,2678.15 609.25,2678.15 611.22,2676.18 605.31,2670.28 605.31,2447.83
AC220V-N on Bottom Layer "Top Layer-No Net 1" (solid, remove dead copper, pour order 54): 1594.49,1654.53 937.99,1654.53 920.28,1672.24 920.28,2058.07 933.07,2070.87 1598.43,2070.87 1591.54,2063.98 1591.54,1653.54
AC220V-N on Bottom Layer "Bottom Layer-No Net" (solid, pour order 72): 2514.76,2047.24 2505.91,2056.1 2505.91,2920.28 1812.99,2920.28 1774.61,2881.89 1774.61,2041.34 1771.65,2038.39 1779.53,2030.51 2511.81,2030.51
DGND on Top Layer "Top Layer-No Net 1" (solid, remove dead copper, pour order 80): 7.87,1480.32 11.81,1484.25 2562.01,1484.25 2562.01,-35.43 2558.07,-39.37 2547.24,-28.54 -38.39,-28.54 -38.39,1462.6 -16.73,1484.25

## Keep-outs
Keep-Out Layer:
  lines w10: 0,-14.08 2519.69,-14.08 2519.69,3187.99 0,3187.99 0,-14.08

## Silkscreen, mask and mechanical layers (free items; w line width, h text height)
Top Overlay:
  text "AC~IN" at 157.48,3100.39 h30
  text "AC~OUT" at 1883.86,3085.63 h30
  text "+5V" at 1695.87,2376.97 h30 r90
  text "GND" at 1701.77,2223.43 h30 r90
  text "NRST" at 2218.5,661.42 h30
  text "3.3v" at 2217.52,571.85 h30
  text "SWCLK" at 2191.93,472.44 h30
  text "SWDIO" at 2198.82,371.06 h30
  text "DGND" at 2216.54,274.61 h30
  text "UT2_TX" at 2173.23,167.32 h30
  text "UT2_RX" at 2162.4,69.88 h30
Bottom Overlay:
  text "scu/i3r/wsnlab" at 2433.07,3060.04 h60
  text "powerplug by wang.w" at 2454.72,2838.58 h60
  text "2018.8.31" at 2447.83,2657.48 h60
Mechanical 1:
  lines w30: 97.44,1929.13 97.44,2674.21

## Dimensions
0,3284.45 to 2518.7,3303.15 on Top Overlay
-110.24,-16.73 to -94.49,3187.01 on Top Overlay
